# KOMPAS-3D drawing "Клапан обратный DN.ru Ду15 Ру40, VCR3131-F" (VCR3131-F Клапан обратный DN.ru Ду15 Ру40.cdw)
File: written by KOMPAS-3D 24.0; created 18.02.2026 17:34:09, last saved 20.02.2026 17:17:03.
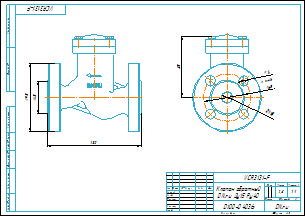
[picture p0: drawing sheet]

Document properties: артикул: D100-04036; Автор: R2D2; Форматы листов документа: A3; Полное имя файла: VCR3131-F Клапан обратный DN.ru Ду15 Ру40.m3d; Масса: 2.8; Наименование: Клапан обратный DN.ru Ду15 Ру40; Количество листов документа: 1; Примечание: D100-04036; Организация: DN.ru

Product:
- Body: Тело 3  | qty 1
    Масса: 3.336756
- Part/product: Клапан обратный DN.ru Ду15 Ру40  | designation VCR3131-F
    Масса: 2.8
    Форматы листов документа: A3
    Примечание: D100-04036
    additional columns: D100-04036

Views: Вид 1, Спереди, Проекционный вид 2
Referenced files in E:\Работа\Зайцев\VCR3131-F Клапан обратный DN.ru Ду15-300\DN15\: VCR3131-F Клапан обратный DN.ru Ду15 Ру40.m3d
Referenced files in E:\Работа\Зайцев\Для компаса\: чертеж DN.ru.cdt
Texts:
  VCR3131-F
  чертеж DN.ru.cdt
  Клапан обратный
  DN.ru Ду15 Ру40
  prop
  Клапан обратный DN.ru Ду15 Ру40
  VCR3131-F Клапан обратный DN.ru Ду15 Ру40
Dimensions and other numbers on the sheet: 0; 3; 2; 4; 65; 15; 85; 14; 4 отв.; 130; 95; 45; 1:1; 1; 2,8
